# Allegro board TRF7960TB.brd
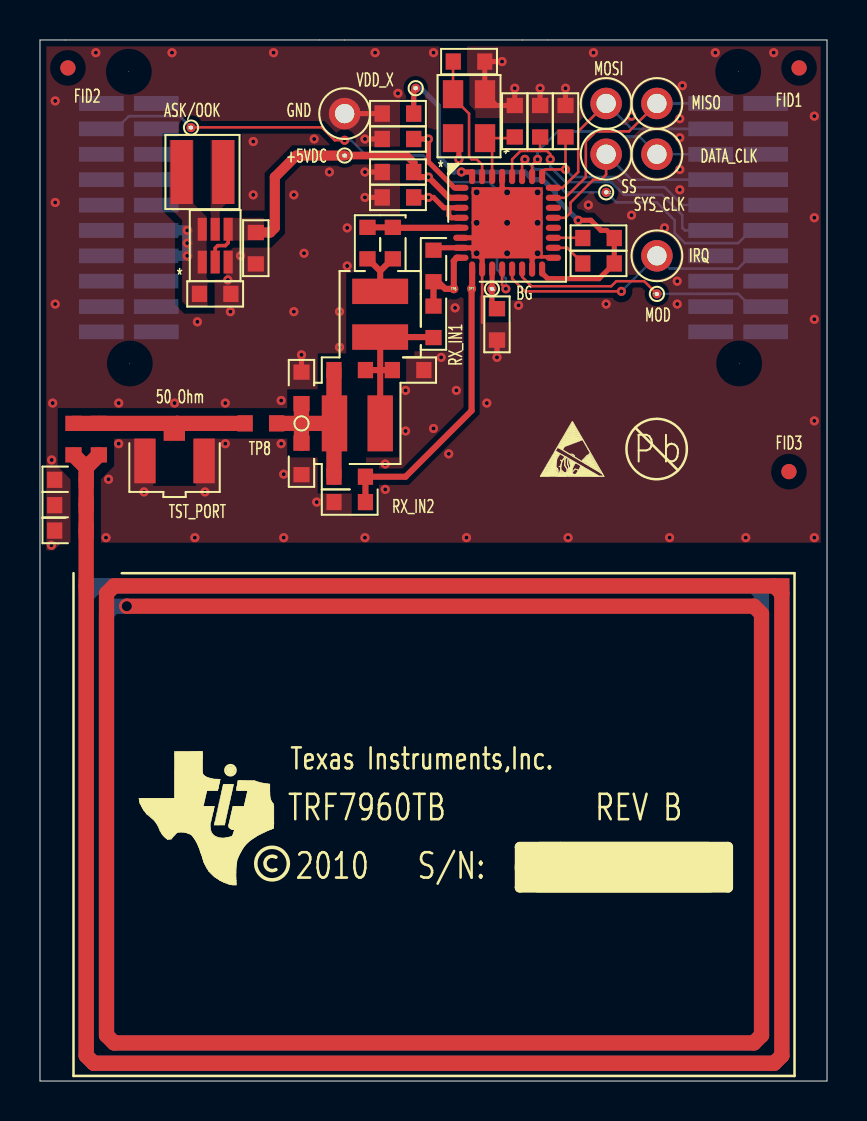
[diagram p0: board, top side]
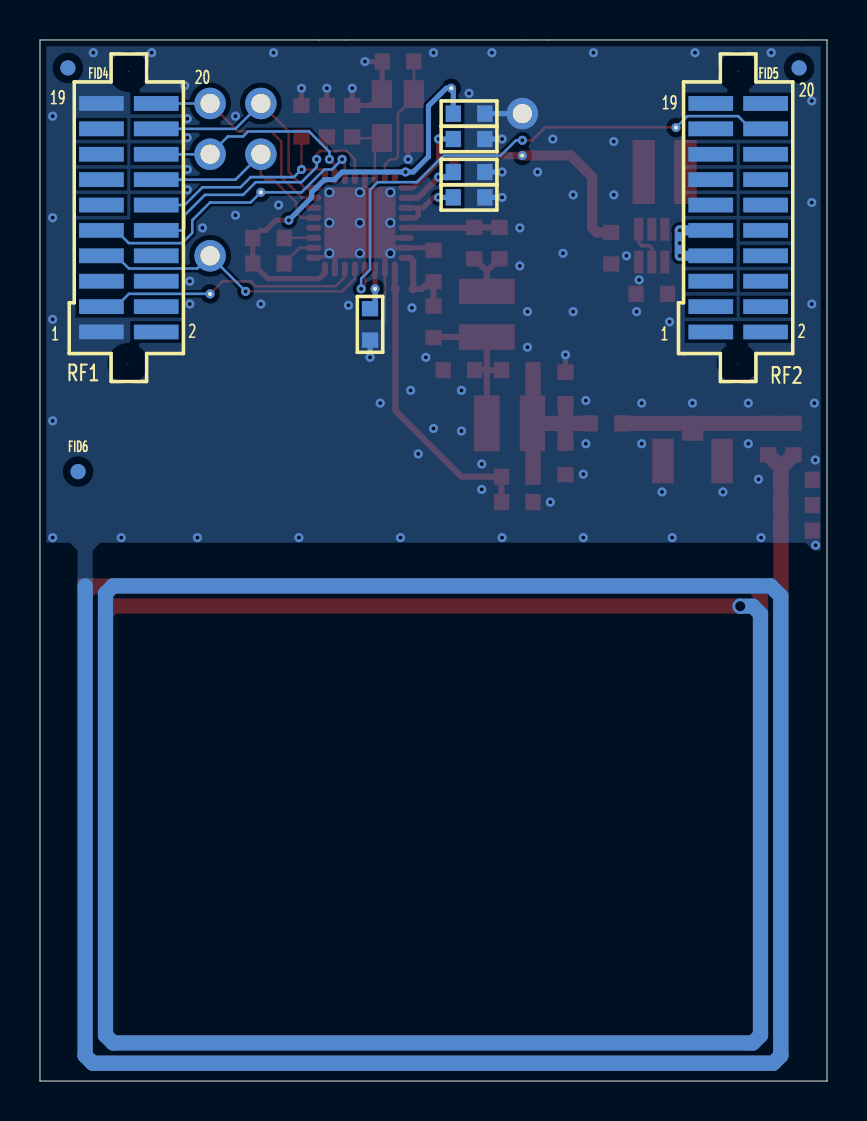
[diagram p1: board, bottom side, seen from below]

Outline 39.37 x 52.07 mm; copper layers: TOP, BOTTOM. Coordinates in mm from the lower left corner of the outline.
Outline path: 0,52.07 39.37,52.07 39.37,0 0,0 0,52.07

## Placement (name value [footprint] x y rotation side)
ANT1  0.950uH  [RFID_ANT_COIL_1P4X1P0]  19.71 12.83 0 top
C1  2.2uF  [0603]  17.91 45.47 180 top
C2  0.01uF  [0603]  17.91 45.47 180 bottom
C3  2.2uF  [0603]  17.91 48.39 180 top
C4  0.01uF  [0603]  17.91 48.39 180 bottom
C5  2.2uF  [0603]  22.86 37.85 270 top
C6  0.01uF  [0603]  22.86 37.85 270 bottom
C7  2.2uF  [0603]  17.91 44.2 180 top
C8  0.01uF  [0603]  17.91 44.2 180 bottom
C9  2.2uF  [0603]  17.91 47.12 180 top
C10  0.01uF  [0603]  17.91 47.12 180 bottom
C11  27pF  [0603]  23.75 48.01 90 top
C12  27pF  [0603]  21.46 50.99 0 top
C13  1500pF  [0603]  16.38 41.91 270 top
C14  1500pF  [0603]  17.65 41.91 270 top
C15  1200pF  [0603]  19.68 37.97 90 top
C16  1200pF  [0603]  19.68 40.77 90 top
C17  680pF  [0603]  18.41 35.56 0 top
C18  10pF  [0603]  15.49 35.56 180 top
C19  220pF  [0603]  15.49 30.23 0 top
C20  680pF  [0603]  15.49 28.96 180 top
C21  100pF  [0603]  13.08 34.67 90 top
C22  27pF  [0603]  13.08 31.11 270 top
C23  68pF  [0603]  1.68 32.11 270 top
C24  82pF  [0603]  1.52 28.8 180 top
C25  10uF  [0603]  10.79 41.66 270 top
C26  10uF  [0603]  8.76 39.37 0 top
C27  1pF  [0603]  2.95 32.11 270 top
C28  2pF  [0603]  1.52 27.53 0 top
FID1  -  [unnamed#2]  37.97 50.67 270 top
FID2  -  [unnamed#2]  1.4 50.67 270 top
FID3  -  [unnamed#2]  37.47 30.48 270 top
FID4  -  [unnamed#2]  37.97 50.67 90 bottom
FID5  -  [unnamed#2]  1.4 50.67 90 bottom
FID6  -  [unnamed#2]  37.47 30.48 90 bottom
J1  COAXIAL  [CON_COAXIAL_UFL-R-SMT]  6.73 31.01 180 top
L1  150nH  [IND_1008PS]  17.02 38.35 90 top
L2  330nH  [IND_1008PS]  15.88 32.89 0 top
L4  4.7uH  [IND_SM_EPL3015]  8.13 45.47 180 top
NOREF  -  []  0 0 90 top
NOREF#2  -  []  0 0 90 top
NOREF#3  -  []  0 0 0 top
NOREF#4  -  []  0 0 0 top
OSC1  13.560MHz  [OSC_4_SM_132X104X47]  21.46 48.26 90 top
P1  SFM-110-02-L-D-A  [CON_SMVT_2X10_50_F_SFM_FLIP_CC]  34.92 43.18 90 bottom
P2  SFM-110-02-L-D-A  [CON_SMVT_2X10_50_F_SFM_FLIP_CC]  4.45 43.18 90 bottom
R1  10k  [0603]  27.94 42.16 180 top
R2  10k  [0603]  27.94 40.89 180 top
R3  10k  [0603]  25.02 48.01 270 top
R4  10k  [0603]  26.29 48.01 270 top
R5  0  [0603]  11.05 32.89 0 top
R6  680  [0603]  1.52 30.07 0 top
TP1  TESTVIA_018  [TP_VIA_018RND008]  15.24 46.29 0 top
TP2  TESTVIA_018  [TP_VIA_018RND008]  18.8 49.66 0 top
TP3  TESTVIA_018  [TP_VIA_018RND008]  22.61 39.62 0 top
TP4  TESTVIA_018  [TP_VIA_018RND008]  7.56 47.69 0 top
TP5  Black  [TP_THVT_060_RND]  15.24 48.39 0 top
TP6  TESTPAD_018  [TP_VIA_018RND]  20.7 39.62 0 top
TP7  TESTPAD_018  [TP_VIA_018RND]  21.59 39.62 0 top
TP8  TESTPAD_018  [TP_VIA_018RND]  13.08 32.89 0 top
TP9  TESTVIA_018  [TP_VIA_018RND008]  30.86 39.37 0 top
TP10  Gray  [TP_THVT_060_RND]  30.86 41.27 0 top
TP11  TESTVIA_018  [TP_VIA_018RND008]  28.32 44.45 0 top
TP12  Black  [TP_THVT_060_RND]  30.86 48.9 0 top
TP13  Blue  [TP_THVT_060_RND]  28.32 48.9 0 top
TP14  Green  [TP_THVT_060_RND]  28.32 46.35 0 top
TP15  Brown  [TP_THVT_060_RND]  30.86 46.35 0 top
U1  TRF7960RHB  [PQFN_32_203X203X40_P5MM]  23.37 42.93 0 top
U2  TPS61222DCKT  [SOP_6_85X55_26]  8.76 41.78 0 top

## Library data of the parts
ANT1 = RFID_ANT_COIL_1p4x1p0
C1-C28 = CAP0603
J1 = CON_COAXIAL_UFL-R-SMT
L1 L2 = 1008PS_102KLV_1p0uH
L4 = IND_EPL3015_4.7uH
OSC1 = XTAL_ITTI_1300225_13p560MHz
P1 P2 = CON_SMVT_2x10_50_F_SFM_FLIP_CC
R1-R6 = RES0603
TP1-TP4 TP9 TP11 = TESTVIA_018
TP5 TP12 = TESTLOOP_BLACK
TP6-TP8 = TESTPAD_018
TP10 = TESTLOOP_GREY
TP13 = TESTLOOP_BLUE
TP14 = TESTLOOP_GREEN
TP15 = TESTLOOP_BROWN
U1 = trf7960rhbt_33
U2 = TPS61220DCKT

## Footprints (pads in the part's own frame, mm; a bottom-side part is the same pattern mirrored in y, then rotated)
0603
  rect 0.762x0.813 smd: 1(-0.787,0) 2(0.787,0)
CON_COAXIAL_UFL-R-SMT
  rect 1.067x2.235 smd: 1(-1.48,0) 3(1.48,0)
  rect 1.067x1.067 smd: 2(0.01,-1.54)
CON_SMVT_2X10_50_F_SFM_FLIP_CC
  round 0.025 hole 1.346 unplated: (-7.303,0.051) (7.303,0)
  rect 0.737x2.235 smd: 1(-5.715,1.372) 2(-5.715,-1.372) 3(-4.445,1.372) 4(-4.445,-1.372) 5(-3.175,1.372) 6(-3.175,-1.372) 7(-1.905,1.372) 8(-1.905,-1.372) 9(-0.635,1.372) 10(-0.635,-1.372) 11(0.635,1.372) 12(0.635,-1.372) 13(1.905,1.372) 14(1.905,-1.372) 15(3.175,1.372) 16(3.175,-1.372) 17(4.445,1.372) 18(4.445,-1.372) 19(5.715,1.372) 20(5.715,-1.372)
IND_1008PS
  rect 1.27x2.794 smd: 1(-1.143,0) 2(1.143,0)
IND_SM_EPL3015
  rect 1.118x3.2 smd: 1(-1.041,0) 2(1.041,0)
OSC_4_SM_132X104X47
  rect 1.397x1.016 smd: 1(-1.1,-0.8) 2(1.1,-0.8) 3(1.1,0.8) 4(-1.1,0.8)
PQFN_32_203X203X40_P5MM
  oval 0.762x0.305 smd: 1(-2.315,1.75) 2(-2.315,1.25) 3(-2.315,0.75) 4(-2.315,0.25) 5(-2.315,-0.25) 6(-2.315,-0.75) 7(-2.315,-1.25) 8(-2.315,-1.75) 17(2.315,-1.75) 18(2.315,-1.25) 19(2.315,-0.75) 20(2.315,-0.25) 21(2.315,0.25) 22(2.315,0.75) 23(2.315,1.25) 24(2.315,1.75)
  oval 0.305x0.762 smd: 9(-1.75,-2.315) 10(-1.25,-2.315) 11(-0.75,-2.315) 12(-0.25,-2.315) 13(0.25,-2.315) 14(0.75,-2.315) 15(1.25,-2.315) 16(1.75,-2.315) 25(1.75,2.315) 26(1.25,2.315) 27(0.75,2.315) 28(0.25,2.315) 29(-0.25,2.315) 30(-0.75,2.315) 31(-1.25,2.315) 32(-1.75,2.315)
  rect 3.556x3.556 smd: 33(0,0)
RFID_ANT_COIL_1P4X1P0
  rect 0.762x0.762 smd: 1(-17.399,11.938) 2(17.399,11.938)
SOP_6_85X55_26
  rect 0.457x1.143 smd: 1(-0.65,-0.82) 2(0,-0.82) 3(0.65,-0.82) 4(0.65,0.82) 5(0,0.82) 6(-0.65,0.82)
TP_THVT_060_RND
  round 1.575 hole 0.965: 1(0,0)
TP_VIA_018RND
  round 0.457 smd: 1(0,0)
TP_VIA_018RND008
  round 0.457 hole 0.203: 1(0,0)
unnamed#2
  round 0.762 smd: (0,0)

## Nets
+5VDC: C1.1 C2.1 C25.1 TP1.1(TP) U1.2(VIN) U2.2(FB) U2.4(VOUT)
GND: ANT1.1(IN) ANT1.2(GND) C1.2 C2.2 C3.2 C4.2 C5.2 C6.2 C7.2 C8.2 C9.2 C10.2 C11.2 C12.2 C16.2 C17.2 C20.2 C21.2 C22.2 C23.2 C24.1 C24.2 C25.2 C26.2 C27.2 C28.1 C28.2 J1.1(GND#1) J1.3(GND#3) OSC1.2(GND#2) OSC1.4(GND#4) P1.1 P1.19 R3.1 R4.1 R6.1 R6.2 TP5.1(TP) U1.6(VSS_PA) U1.7(VSS_RX) U1.10(VSS) U1.15(VSS_A) U1.17(I/O_0) U1.29(VSS_D) U1.33(TH_PAD) U2.3(GND)
VDD: C7.1 C8.1 U1.3(VDD_RF) U1.4(VDD_PA)
VDD_X: C3.1 C4.1 R1.1 R2.1 TP2.1(TP) U1.16(VDD_I/O) U1.32(VDD_X)
VIN: C26.1 L4.2 P2.7 P2.9 U2.1(VIN) U2.6(EN)
BG: C5.1 C6.1 TP3.1(TP) U1.11(BAND_GAP)
LD: L4.1 U2.5(L)
N323772: P1.10 R3.2 U1.28(EN)
N323788: P1.12 R4.2 U1.25(EN2)
N323826: C13.1 C14.1 U1.5(TX_OUT)
N323846: C19.2 C20.1 TP7.1(TP) U1.9(RX_IN2)
N323954: C15.2 C16.1 TP6.1(TP) U1.8(RX_IN1)
N323966: C13.2 C14.2 L1.2
N324254: C18.2 C19.1 C21.1 C22.1 L2.1 R5.2 TP8.1(TP)
N324450: C9.1 C10.1 U1.1(VDD_A)
N324500: C12.1 OSC1.3(XTAL2) U1.31(OSC_IN)
N324566: C11.1 OSC1.1(XTAL1) U1.30(OSC_OUT)
N324574: R2.2 U1.18(I/O_1)
N324708: R1.2 U1.19(I/O_2)
N324984: C15.1 C17.1 C18.1 L1.1 L2.2
N347285: P1.14 TP14.1(TP) U1.21(SLAVE SELECT)
N347465: P1.16 TP15.1(TP) U1.26(DATA_CLK)
N347647: P1.18 TP13.1(TP) U1.24(MOSI)
N347831: P1.20 TP12.1(TP) U1.23(MISO)
N351007: P1.9 TP11.1(TP) U1.27(SYS_CLK)
N351658: P1.7 TP10.1(TP) U1.13(IRQ)
N352268: P1.3 TP9.1(TP) U1.14(MOD)
N354603: P2.18 TP4.1(TP) U1.12(ASK/OOK)
N400459: C23.1 C27.1 J1.2 R5.1

Pads without a net: P1 2 4 5 6 8 11 13 15 17; P2 1 2 3 4 5 6 8 10 11 12 13 14 15 16 17 19 20; U1 20 22

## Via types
v1: diameter 0.457, hole 0.203, TOP to BOTTOM, 103 vias
v2: diameter 0.762, hole 0.508, TOP to BOTTOM, 1 via
v3: diameter 0.508, hole 0.305, TOP to BOTTOM, 9 vias

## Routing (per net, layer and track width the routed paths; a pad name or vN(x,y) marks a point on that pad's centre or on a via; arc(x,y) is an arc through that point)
+5VDC: length 17.5
  TOP w0.178: U2.4 9.41,41.93 9.27,41.78 8.89,41.78 8.76,41.66 U2.2
  TOP w0.305: U1.2 20.47,44.18 v1(19.43,45.21) 18.95,45.21 C1.1
  TOP w0.381: TP1.1 18.35,46.29 18.69,45.95 C1.1
  TOP w0.508: TP1.1 12.83,46.29 11.75,45.21 11.75,42.67 11.52,42.44 C25.1
  BOTTOM w0.305: C1.1 18.95,45.21 v1(19.43,45.21)
GND: length 455.6
  TOP w0.127: U1.10 22.12,37.93
  TOP w0.178: v3(24.89,41.4) 25.07,41.22 25.34,41.22 25.39,41.18 U1.17
  TOP w0.254: C21.2 v1(13.08,36.32) ; C5.2 v1(22.86,36.2) ; U1.29 23.12,44.7 v3(23.37,44.45) ; C7.2 v1(16.26,44.2) ; R3.1 v1(25.02,49.66) ; v1(20.95,46.1) 20.95,46.87 OSC1.4 ; U1.10 22.12,41.13 v3(21.84,41.4) 21.57,41.68 U1.7 19.81,41.68 C16.2 ; U1.15 24.62,41.13 v3(24.89,41.4) ; v1(23.75,49.66) C11.2 22.83,48.79 OSC1.2 22.25,49.37 C12.2 v1(23.11,50.99) ; R4.1 v1(26.29,49.66) ; v3(23.37,42.93) 22.62,42.18 U1.6 ; C1.2 v1(16.26,45.47) ; C9.2 v1(16.26,47.12) ; C3.2 TP5.1
  TOP w0.762: C23.2 2.31,30.68 ; 2.31,30.68 R6.2 C24.1 C28.2 ANT1.1 2.31,1.27 2.69,0.89 36.73,0.89 37.11,1.27 37.11,24.38 36.73,24.77 3.71,24.77 3.33,24.38 3.33,2.29 3.71,1.91 35.71,1.91 36.09,2.29 36.09,23.37 35.71,23.75 v2(4.34,23.75) ; 2.31,30.68 C27.2
  BOTTOM w0.254: C9.2 v1(16.26,47.12) ; C5.2 v1(22.86,36.2) ; C3.2 TP5.1 ; C1.2 v1(16.26,45.47) ; C7.2 v1(16.26,44.2)
  BOTTOM w0.762: v2(4.34,23.75) 3.71,23.75 3.33,23.37 3.33,2.29 3.71,1.91 35.71,1.91 36.09,2.29 36.09,24.38 35.71,24.77 2.82,24.77 2.31,24.26 2.31,1.27 2.69,0.89 3.07,0.89 36.73,0.89 37.11,1.27 ANT1.2
  vias: v1(0.64,33.91) v1(0.58,31.06) v1(0.57,26.8) v1(0.76,49.02) v1(0.76,43.94) v1(0.76,38.86) v1(2.79,51.44) v1(3.3,27.18) v1(3.43,30.1) v1(3.94,33.91) v1(3.94,31.88) v1(5.21,29.46) v1(6.6,51.44) v1(6.73,33.91) v1(7.75,27.18) v1(7.87,37.97) v1(8.26,29.46) v1(9.27,33.91) v1(9.27,31.88) v1(9.4,40.07) v1(9.53,38.48) v1(10.03,41.27) v1(10.67,46.99) v1(10.67,44.32) v1(11.68,51.44) v1(12.06,34.04) v1(12.06,31.88) v1(12.19,30.35) v1(12.19,27.18) v1(12.7,44.32) v1(12.7,38.48) v1(13.21,41.4) v1(13.72,47.12) v1(13.84,28.96) v1(14.48,45.47) v1(14.99,38.48) v1(14.99,36.7) v1(15.37,42.67) v1(15.37,40.77) v1(16.26,27.18) v1(16.76,51.44) v1(17.27,30.86) v1(17.27,29.59) v1(17.91,49.4) v1(18.29,34.54) v1(18.29,32.51) v1(19.68,51.44) v1(19.68,32.64) v1(20.07,36.2) v1(20.45,31.37) v1(20.76,38.67) v1(20.83,34.54) v1(21.34,27.18) v1(22.35,33.91) v1(23.94,38.8) v1(26.42,27.18) v1(27.43,43.81) v1(27.69,51.44) v1(28.32,38.86) v1(29.59,48.26) v1(29.59,43.31) v1(31.24,42.67) v1(31.5,27.18) v1(31.88,40.01) v1(31.88,38.86) v1(32,48.13) v1(32,47.18) v1(32,45.59) v1(32,44.58) v1(32.13,49.78) v1(33.78,51.44) v1(35.31,27.18) v1(36.7,51.44) v1(38.73,48.26) v1(38.73,43.18) v1(38.73,38.1) v1(38.73,33.02) v1(38.73,27.18) v3(21.84,44.45) v3(21.84,42.93) v3(23.37,41.4) v3(24.89,44.45) v3(24.89,42.93)
VDD: length 4.3
  TOP w0.254: U1.4 20.58,43.18 20.45,43.31 20.45,43.68 ; C7.1 v1(19.43,44.2) 19.68,44.2 20.2,43.68 20.45,43.68 ; 20.45,43.68 U1.3
  BOTTOM w0.254: v1(19.43,44.2) C7.1
VDD_X: length 23.6
  TOP w0.254: C3.1 18.69,49.56 TP2.1 ; U1.16 25.12,40.41 25.4,40.13 27.97,40.13 R2.1 R1.1 28.35,42.55 28.07,42.55 27.56,43.05 v1(26.92,43.05) ; v1(21.08,45.47) 21.62,45.47 U1.32
  BOTTOM w0.254: C3.1 18.69,49.56 TP2.1 19.05,49.66 19.94,48.77 19.94,46.23 20.7,45.47 v1(21.08,45.47) 21.97,45.47 24.26,45.47 24.64,45.09 25.15,45.09 25.78,44.45 25.78,44.2 v1(26.92,43.05)
VIN: length 4.4
  BOTTOM w0.508: P2.9 v1(7.37,42.55) v1(7.37,41.91) v1(7.37,41.27) P2.7
BG: length 3.2
  TOP w0.254: C5.1 22.61,38.89 TP3.1 22.62,39.64 U1.11
  BOTTOM w0.254: TP3.1 22.61,38.89 C5.1
N323772: length 14.1
  TOP w0.127: 25.02,46.52 24.04,46.52 23.62,46.1 U1.28 ; 25.02,46.52 25.36,46.52 25.53,46.35 v1(25.53,46.1) ; 25.02,46.52 R3.2
  BOTTOM w0.127: v1(25.53,46.1) 25.53,45.72 26.29,44.96 28.57,44.96 29.21,44.32 31.11,44.32 32.13,43.31 32.13,42.67 32.26,42.55 P1.10
N323788: length 11.1
  TOP w0.127: U1.25 25.12,45.44 25.27,45.59 v1(26.29,45.59) R4.2
  BOTTOM w0.127: P1.12 32.13,43.81 31.24,44.7 29.34,44.7 28.83,45.21 26.67,45.21 v1(26.29,45.59)
N323826: length 4.7
  TOP w0.305: U1.5 17.8,42.68 C14.1 C13.1
N323846: length 15
  TOP w0.305: C20.1 C19.2 18.29,30.23 21.59,33.53 TP7.1 21.62,39.65 U1.9
N323954: length 4.2
  TOP w0.305: U1.8 20.86,41.18 20.7,41.02 TP6.1 20.27,39.62 19.91,39.98 C16.1 C15.2
N323966: length 2.8
  TOP w0.305: C13.2 16.41,41.12 17.02,40.51 ; L1.2 17.02,40.51 ; 17.02,40.51 17.63,41.12 C14.2
N324254: length 10.2
  TOP w0.762: TP8.1 C22.1 ; TP8.1 L2.1 ; TP8.1 R5.2 ; TP8.1 C21.1 ; L2.1 14.71,32.87 C19.1 ; L2.1 14.71,32.92 C18.2
N324450: length 4.8
  TOP w0.254: C9.1 v1(19.43,47.12) 19.43,45.97 20.73,44.68 U1.1
  BOTTOM w0.254: v1(19.43,47.12) C9.1
N324500: length 6.5
  TOP w0.127: U1.31 22.12,45.83 21.84,46.1 21.59,46.1 21.46,46.23 21.46,48.39 20.66,49.19 OSC1.3 20.66,50.98 C12.1
N324566: length 3.6
  TOP w0.127: C11.1 23.69,47.16 OSC1.1 22.62,46.81 U1.30
N324574: length 1.8
  TOP w0.127: U1.18 26.37,41.68 R2.2
N324708: length 1.5
  TOP w0.127: R1.2 27.14,42.18 U1.19
N324984: length 8.3
  TOP w0.305: 17.02,35.56 L2.2 ; 17.02,35.56 C17.1 ; 17.02,35.56 C18.1 ; 17.02,35.56 L1.1 19.66,37.21 C15.1
N347285: length 10.6
  TOP w0.127: TP14.1 28.32,45.34 28.07,45.09 27.69,45.09 26.54,43.94 26.54,43.43 26.29,43.18 U1.21
  BOTTOM w0.127: P1.14 29.59,45.09 TP14.1
N347465: length 10.9
  TOP w0.127: v1(24.89,46.1) 24.62,45.83 U1.26
  BOTTOM w0.127: v1(24.89,46.1) 24.89,46.48 25.91,47.5 28.96,47.5 29.21,47.24 29.97,47.24 TP15.1 P1.16
N347647: length 11.3
  TOP w0.127: U1.24 26.13,44.68 26.92,45.47 26.92,47.5 TP13.1
  BOTTOM w0.127: P1.18 29.59,47.62 TP13.1
N347831: length 10.9
  TOP w0.127: TP12.1 29.46,47.5 27.81,47.5 27.3,46.99 27.3,45.21 26.27,44.18 U1.23
  BOTTOM w0.127: 33.55,48.9 TP12.1
N351007: length 15.3
  TOP w0.127: v1(24.26,46.1) 24.12,45.96 U1.27
  BOTTOM w0.127: v1(24.26,46.1) 24.76,45.59 25.15,45.59 26.29,44.45 TP11.1 28.83,43.94 30.86,43.94 31.75,43.05 31.75,42.42 32.26,41.91 34.92,41.91 35.56,42.55 P1.9
N351658: length 14.7
  TOP w0.127: v1(29.08,39.5) 24.26,39.5 23.62,40.14 U1.13
  BOTTOM w0.127: v1(29.08,39.5) TP10.1 31.5,40.64 34.92,40.64 35.56,41.27 P1.7
N352268: length 13.4
  TOP w0.127: TP9.1 30.23,40.01 28.83,40.01 28.57,39.75 24.59,39.75 24.12,40.22 U1.14
  BOTTOM w0.127: P1.3 35.56,38.73 34.92,39.37 TP9.1
N354603: length 27.8
  TOP w0.127: v1(23.3,39.62) 23.11,39.81 23.11,40.61 U1.12 ; v1(15.24,47.05) 14.74,47.05 14.1,47.7 7.57,47.7 TP4.1
  BOTTOM w0.127: v1(23.3,39.62) 23.3,40.13 22.86,40.58 22.86,44.58 22.48,44.96 20.51,44.96 19.18,46.29 16.32,46.29 15.56,47.05 v1(15.24,47.05) ; P2.18 3.81,47.62 4.45,48.26 6.99,48.26 TP4.1
N400459: length 9
  TOP w0.762: 6.86,32.89 R5.1 ; 6.86,32.89 C27.1 C23.1 ; 6.86,32.89 6.72,32.76 J1.2

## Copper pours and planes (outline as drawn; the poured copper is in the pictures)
+5VDC on TOP: 9.21,42.04 11.2,42.04 11.2,43.18 9.21,43.18
GND on TOP: 3.05,26.92 3.05,30.1 3.71,30.76 3.71,32.13 12.45,32.13 12.45,33.66 0.89,33.66 0.89,30.73 1.52,30.1 1.52,26.92 1.08,26.92 0.7,26.54 0.32,26.54 0.32,51.75 39.05,51.75 39.05,26.92 ; 12 cut-outs
GND on BOTTOM: 0.32,51.75 39.05,51.75 39.05,26.92 37.87,26.92 37.49,26.54 37.49,24.38 36.73,24.38 36.73,26.54 36.35,26.92 1.08,26.92 0.7,26.54 0.32,26.54 ; 8 cut-outs
VIN on TOP: 7.68,43.88 7.68,47.07 6.48,47.07 6.48,43.69 7.11,43.05 7.11,38.99 7.37,38.73 8.38,38.73 8.38,40.13 8.33,40.18 8.33,43.23
LD on TOP: 9.73,43.87 9.3,43.87 8.99,43.56 8.99,42.04 8.53,42.04 8.53,47.07 9.73,47.07

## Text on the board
BOTTOM: LAYER 2 - SECONDARY SIDE | 2
Ref Des/Assembly Bottom: ASSEMBLY - SECONDARY SIDE | 2
Board Geometry/Soldermask Bottom: SOLDERMASK - SECONDARY SIDE | 4
Package Geometry/Pastemask Bottom: SOLDERPASTE - SECONDARY SIDE | 8
Ref Des/Silkscreen Bottom: SILKSCREEN - SECONDARY SIDE | 6
User.Comments: TI_AEC-RFID | 8 | TRF7960TB | TEXAS INSTRUMENTS | B | 06/10/2010
TOP: LAYER 1 - PRIMARY SIDE | 1
Ref Des/Assembly Top: ASSEMBLY - PRIMARY SIDE | 1 | 2
Board Geometry/Soldermask Top: SOLDERMASK - PRIMARY SIDE | 3
Package Geometry/Pastemask Top: SOLDERPASTE - PRIMARY SIDE | 7
Ref Des/Silkscreen Top: Texas Instruments,Inc. | TRF7960TB | 2010 | S/N: | REV B | SILKSCREEN - PRIMARY SIDE | 5
DIMENSION: FR4-370 | Plate to 1.5 oz min Layer 2 | Core 0.058" | Plate to 1.5 oz min Layer 1 | 0.5oz / 0.5oz Layer 1 & 2 | LAYER 1 | LAYER 2 | PRIMARY SIDE | SECONDARY SIDE | DELIVERED WITH EACH LOT. | FAB NOTES: | 1. ALL DIMENSIONS ARE IN INCHES, UNLESS | OTHERWISE NOTED. | 2. THE PWB SHALL BE FABRICATED TO IPC-6012, | CLASS 2 AND WORKMANSHIP SHALL CONFORM TO | IPC-A-600, CLASS 2. CURRENT REVISIONS. | 3. BOARD MATERIAL SHALL BE 180 Tg / 340 Td ISOLA | FR-370HR OR EQUIVALENT, RoSH COMPLIANT AND | LEAD FREE ASSEMBLY CAPABLE. BOARD MATERIAL | SHALL MEET OR EXCEED IPC-4101B. | RoSH CERTIFICATE OF CONFORMANCE SHALL BE | 4. BOARD MATERIAL & CONSTRUCTION TO BE U.L. | APPROVED AND MARKED ON THE FINISHED BOARD. | 5. OVERALL BOARD THICKNESS TO BE .062 +/-.005". | AND APPLIES AFTER ALL LAMINATION AND PLATING | PROCESSES, MEASURED FROM COPPER TO COPPER. | 6. MAX. WARP & TWIST TO BE .0075 PER INCH. | 7. BOARD MUST BE ELECTRICALLY TESTED USING | SUPPLIED IPC-D-356 NETLIST. | 8. 30 MIL TRACES ON LAYER 1 ARE 50 OHMS +/- 10%. | THEY ARE REFERANCE TO LAYER 1 GROUND WITH | SOLDERMASK CLEAR AWAY. | IMMERSION GOLD.   NICKEL: 100 MICRO-INCHES MIN. | GOLD: 2-8 MICROINCHES MIN. | 2. PLATE ALL EXPOSED AREAS WITH ELECTROLESS NICKEL | PROCESS NOTES: | 1. APPLY LPI SOLDERMASK OVER BARE COPPER (SMOBC), | COLOR: GREEN. SOLDERMASK SHALL CONFORM TO | IPC-SM-840, CLASS H. CURRENT REV. | 3. SOLDERMASK ARTWORK HAS ZERO (0) OVERSIZED PADS. | FABRICATION VENDOR IS ALLOWED TO ADJUST THE COMPONENT | SOLDERMASK PADS TO MEET THEIR TOOLING REQUIREMENTS. | 4. APPLY NON-CONDUCTIVE LPI SILKSCREEN OR EQUIVALENT PER | THE ARTWORK. COLOR: WHITE. | 5. BOARD MUST BE ELECTRICALLY TESTED USING SUPPLIED | IPC-D-356 NETLIST. | LAYER 1 - PRIMARY SIDE | LAYER 2 - SECONDARY SIDE | LAYER STACK UP: | VIEWED FROM PRIMARY SIDE | FABRICATION DRAWING | 1
DISPLAY_TOP: FIGURE | SIZE | 8.0 | 12.0 | 20.0 | 38.0 | 53.0 | DRILL CHART: TOP to BOTTOM | ALL UNITS ARE IN MILS | TOLERANCE | +3.0/-3.0 | +2.0/-2.0 | PLATED | NON-PLATED | QTY | 109 | 9 | 1 | 6 | 4
